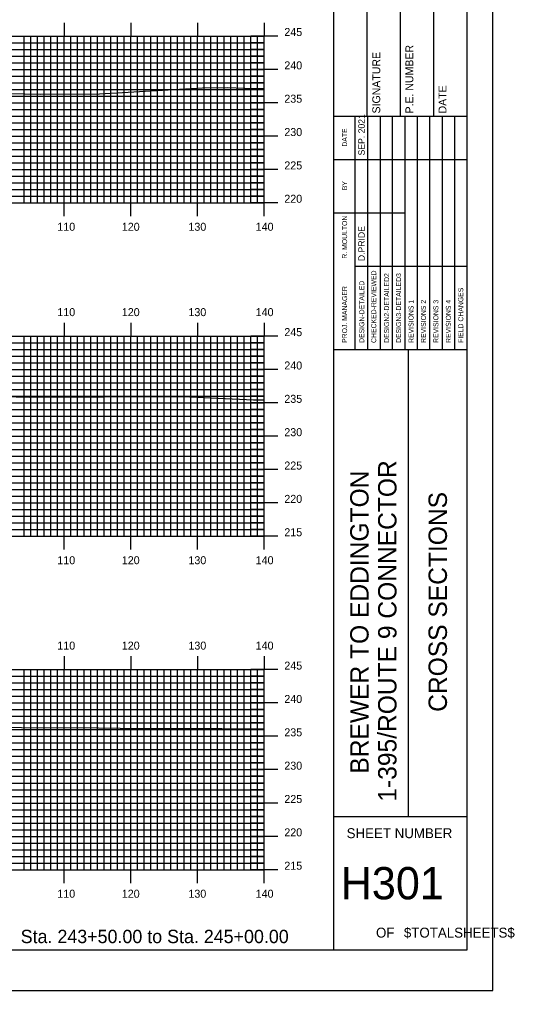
# Model space of a CAD drawing. Extents: x 1802716 to 1803060, y 442591 to 442811.
# Drawn here: x 1802985.4 to 1803059.6, y 442590.5 to 442736.2 of the extents above; entities that cross this region are included whole.
import ezdxf

# ---------------------------------------------------------------- set-up
doc = ezdxf.new("R2010")
doc.units = 0
for name, color, linetype in [('BORDER', 7, 'Continuous'), ('H_V ANNOTATION', 7, 'Continuous'), ('MAJOR', 7, 'Continuous'), ('MINOR', 7, 'Continuous'), ('PLOT BOUNDARY', 7, 'Continuous'), ('S_Roadway_Centerline', 7, 'Continuous')]:
    doc.layers.add(name, color=color, linetype=linetype)

msp = doc.modelspace()

# ---------------------------------------------------------------- linework, layer by layer
at = {"layer": 'BORDER'}
for p, q in [((1803032.51, 442596.67), (1803032.51, 442806.67)), ((1803037.51, 442721.67), (1803037.51, 442738.97)), ((1803042.51, 442721.67), (1803042.51, 442738.97)), ((1803047.51, 442721.67), (1803047.51, 442738.97)), ((1803032.51, 442721.67), (1803052.51, 442721.67)), ((1803032.51, 442686.67), (1803052.51, 442686.67)), ((1803043.7, 442616.67), (1803043.7, 442686.67)), ((1803032.51, 442616.67), (1803052.51, 442616.67))]:
    msp.add_line(p, q, dxfattribs=at)
msp.add_lwpolyline([(1802732.51, 442596.67), (1803052.51, 442596.67), (1803052.51, 442806.67), (1802732.51, 442806.67)], close=True, dxfattribs=at)
for points in [[(1803035.74, 442715.17), (1803035.74, 442721.67)], [(1803037.61, 442686.68), (1803037.61, 442721.67)], [(1803039.47, 442721.67), (1803039.47, 442686.68)], [(1803041.34, 442686.68), (1803041.34, 442721.67)], [(1803043.2, 442686.68), (1803043.2, 442721.67)], [(1803045.06, 442686.68), (1803045.06, 442721.67)], [(1803046.93, 442686.68), (1803046.93, 442721.67)], [(1803048.79, 442686.68), (1803048.79, 442721.67)], [(1803050.65, 442686.68), (1803050.65, 442721.67)], [(1803035.75, 442686.68), (1803035.75, 442720.26)], [(1803032.51, 442715.17), (1803052.51, 442715.17)], [(1803032.51, 442707.17), (1803035.75, 442707.17)], [(1803035.74, 442707.17), (1803043.2, 442707.17)], [(1803035.74, 442699.17), (1803052.51, 442699.17)]]:
    msp.add_lwpolyline(points, dxfattribs=at)
at = {"layer": 'MAJOR'}
for p, q in [((1802992.11, 442735.67), (1802992.11, 442733.67)), ((1803002.11, 442735.67), (1803002.11, 442733.67)), ((1803012.11, 442735.67), (1803012.11, 442733.67)), ((1803022.11, 442735.67), (1803022.11, 442733.67)), ((1802742.11, 442733.67), (1803022.11, 442733.67)), ((1802742.11, 442733.67), (1803022.11, 442733.67)), ((1802992.11, 442708.67), (1802992.11, 442733.67)), ((1803002.11, 442708.67), (1803002.11, 442733.67)), ((1803012.11, 442708.67), (1803012.11, 442733.67)), ((1803024.12, 442733.67), (1803020.11, 442733.67)), ((1803022.11, 442708.67), (1803022.11, 442733.67)), ((1803022.11, 442708.67), (1803022.11, 442733.67)), ((1802742.11, 442728.67), (1803022.11, 442728.67)), ((1803024.12, 442728.67), (1803020.11, 442728.67)), ((1802742.11, 442723.67), (1803022.11, 442723.67)), ((1803024.12, 442723.67), (1803020.11, 442723.67)), ((1802742.11, 442718.67), (1803022.11, 442718.67)), ((1803024.12, 442718.67), (1803020.11, 442718.67)), ((1802742.11, 442713.67), (1803022.11, 442713.67)), ((1803024.12, 442713.67), (1803020.11, 442713.67)), ((1802742.11, 442708.67), (1803022.11, 442708.67)), ((1802742.11, 442708.67), (1803022.11, 442708.67)), ((1802992.11, 442706.66), (1802992.11, 442708.67)), ((1803002.11, 442706.66), (1803002.11, 442708.67)), ((1803012.11, 442706.66), (1803012.11, 442708.67)), ((1803024.12, 442708.67), (1803020.11, 442708.67)), ((1803022.11, 442706.66), (1803022.11, 442708.67)), ((1802992.11, 442690.67), (1802992.11, 442688.67)), ((1803002.11, 442690.67), (1803002.11, 442688.67)), ((1803012.11, 442690.67), (1803012.11, 442688.67)), ((1803022.11, 442690.67), (1803022.11, 442688.67)), ((1802742.11, 442688.67), (1803022.11, 442688.67)), ((1802742.11, 442688.67), (1803022.11, 442688.67)), ((1802992.11, 442658.67), (1802992.11, 442688.67)), ((1803002.11, 442658.67), (1803002.11, 442688.67)), ((1803012.11, 442658.67), (1803012.11, 442688.67)), ((1803024.12, 442688.67), (1803020.11, 442688.67)), ((1803022.11, 442658.67), (1803022.11, 442688.67)), ((1803022.11, 442658.67), (1803022.11, 442688.67)), ((1802742.11, 442683.67), (1803022.11, 442683.67)), ((1803024.12, 442683.67), (1803020.11, 442683.67)), ((1802742.11, 442678.67), (1803022.11, 442678.67)), ((1803024.12, 442678.67), (1803020.11, 442678.67)), ((1802742.11, 442673.67), (1803022.11, 442673.67)), ((1803024.12, 442673.67), (1803020.11, 442673.67)), ((1802742.11, 442668.67), (1803022.11, 442668.67)), ((1803024.12, 442668.67), (1803020.11, 442668.67)), ((1802742.11, 442663.67), (1803022.11, 442663.67)), ((1803024.12, 442663.67), (1803020.11, 442663.67)), ((1802742.11, 442658.67), (1803022.11, 442658.67)), ((1802742.11, 442658.67), (1803022.11, 442658.67)), ((1802992.11, 442656.66), (1802992.11, 442658.67)), ((1803002.11, 442656.66), (1803002.11, 442658.67)), ((1803012.11, 442656.66), (1803012.11, 442658.67)), ((1803024.12, 442658.67), (1803020.11, 442658.67)), ((1803022.11, 442656.66), (1803022.11, 442658.67)), ((1802992.11, 442640.67), (1802992.11, 442638.67)), ((1803002.11, 442640.67), (1803002.11, 442638.67)), ((1803012.11, 442640.67), (1803012.11, 442638.67)), ((1803022.11, 442640.67), (1803022.11, 442638.67)), ((1802742.11, 442638.67), (1803022.11, 442638.67)), ((1802742.11, 442638.67), (1803022.11, 442638.67)), ((1802992.11, 442608.67), (1802992.11, 442638.67)), ((1803002.11, 442608.67), (1803002.11, 442638.67)), ((1803012.11, 442608.67), (1803012.11, 442638.67)), ((1803024.12, 442638.67), (1803020.11, 442638.67)), ((1803022.11, 442608.67), (1803022.11, 442638.67)), ((1803022.11, 442608.67), (1803022.11, 442638.67)), ((1802742.11, 442633.67), (1803022.11, 442633.67)), ((1803024.12, 442633.67), (1803020.11, 442633.67)), ((1802742.11, 442628.67), (1803022.11, 442628.67)), ((1803024.12, 442628.67), (1803020.11, 442628.67)), ((1802742.11, 442623.67), (1803022.11, 442623.67)), ((1803024.12, 442623.67), (1803020.11, 442623.67)), ((1802742.11, 442618.67), (1803022.11, 442618.67)), ((1803024.12, 442618.67), (1803020.11, 442618.67)), ((1802742.11, 442613.67), (1803022.11, 442613.67)), ((1803024.12, 442613.67), (1803020.11, 442613.67)), ((1802742.11, 442608.67), (1803022.11, 442608.67)), ((1802742.11, 442608.67), (1803022.11, 442608.67)), ((1802992.11, 442606.66), (1802992.11, 442608.67)), ((1803002.11, 442606.66), (1803002.11, 442608.67)), ((1803012.11, 442606.66), (1803012.11, 442608.67)), ((1803024.12, 442608.67), (1803020.11, 442608.67)), ((1803022.11, 442606.66), (1803022.11, 442608.67))]:
    msp.add_line(p, q, dxfattribs=at)
at = {"layer": 'MINOR'}
for p, q in [((1802742.11, 442732.67), (1803022.11, 442732.67)), ((1802986.11, 442708.67), (1802986.11, 442733.67)), ((1802987.11, 442708.67), (1802987.11, 442733.67)), ((1802988.11, 442708.67), (1802988.11, 442733.67)), ((1802989.11, 442708.67), (1802989.11, 442733.67)), ((1802990.11, 442708.67), (1802990.11, 442733.67)), ((1802991.11, 442708.67), (1802991.11, 442733.67)), ((1802993.11, 442708.67), (1802993.11, 442733.67)), ((1802994.11, 442708.67), (1802994.11, 442733.67)), ((1802995.11, 442708.67), (1802995.11, 442733.67)), ((1802996.11, 442708.67), (1802996.11, 442733.67)), ((1802997.11, 442708.67), (1802997.11, 442733.67)), ((1802998.11, 442708.67), (1802998.11, 442733.67)), ((1802999.11, 442708.67), (1802999.11, 442733.67)), ((1803000.11, 442708.67), (1803000.11, 442733.67)), ((1803001.11, 442708.67), (1803001.11, 442733.67)), ((1803003.11, 442708.67), (1803003.11, 442733.67)), ((1803004.11, 442708.67), (1803004.11, 442733.67)), ((1803005.11, 442708.67), (1803005.11, 442733.67)), ((1803006.11, 442708.67), (1803006.11, 442733.67)), ((1803007.11, 442708.67), (1803007.11, 442733.67)), ((1803008.11, 442708.67), (1803008.11, 442733.67)), ((1803009.11, 442708.67), (1803009.11, 442733.67)), ((1803010.11, 442708.67), (1803010.11, 442733.67)), ((1803011.11, 442708.67), (1803011.11, 442733.67)), ((1803013.11, 442708.67), (1803013.11, 442733.67)), ((1803014.11, 442708.67), (1803014.11, 442733.67)), ((1803015.11, 442708.67), (1803015.11, 442733.67)), ((1803016.11, 442708.67), (1803016.11, 442733.67)), ((1803017.11, 442708.67), (1803017.11, 442733.67)), ((1803018.11, 442708.67), (1803018.11, 442733.67)), ((1803019.11, 442708.67), (1803019.11, 442733.67)), ((1803020.11, 442708.67), (1803020.11, 442733.67)), ((1803022.11, 442732.67), (1803020.11, 442732.67)), ((1803021.11, 442708.67), (1803021.11, 442733.67)), ((1802742.11, 442731.67), (1803022.11, 442731.67)), ((1803022.11, 442731.67), (1803020.11, 442731.67)), ((1802742.11, 442730.67), (1803022.11, 442730.67)), ((1803022.11, 442730.67), (1803020.11, 442730.67)), ((1802742.11, 442729.67), (1803022.11, 442729.67)), ((1803022.11, 442729.67), (1803020.11, 442729.67)), ((1802742.11, 442727.67), (1803022.11, 442727.67)), ((1803022.11, 442727.67), (1803020.11, 442727.67)), ((1802742.11, 442726.67), (1803022.11, 442726.67)), ((1802742.11, 442725.67), (1803022.11, 442725.67)), ((1803022.11, 442726.67), (1803020.11, 442726.67)), ((1803022.11, 442725.67), (1803020.11, 442725.67)), ((1802742.11, 442724.67), (1803022.11, 442724.67)), ((1803022.11, 442724.67), (1803020.11, 442724.67)), ((1802742.11, 442722.67), (1803022.11, 442722.67)), ((1803022.11, 442722.67), (1803020.11, 442722.67)), ((1802742.11, 442721.67), (1803022.11, 442721.67)), ((1803022.11, 442721.67), (1803020.11, 442721.67)), ((1802742.11, 442720.67), (1803022.11, 442720.67)), ((1802742.11, 442719.67), (1803022.11, 442719.67)), ((1803022.11, 442720.67), (1803020.11, 442720.67)), ((1803022.11, 442719.67), (1803020.11, 442719.67)), ((1802742.11, 442717.67), (1803022.11, 442717.67)), ((1802742.11, 442716.67), (1803022.11, 442716.67)), ((1803022.11, 442717.67), (1803020.11, 442717.67)), ((1803022.11, 442716.67), (1803020.11, 442716.67)), ((1802742.11, 442715.67), (1803022.11, 442715.67)), ((1803022.11, 442715.67), (1803020.11, 442715.67)), ((1802742.11, 442714.67), (1803022.11, 442714.67)), ((1803022.11, 442714.67), (1803020.11, 442714.67)), ((1802742.11, 442712.67), (1803022.11, 442712.67)), ((1803022.11, 442712.67), (1803020.11, 442712.67)), ((1802742.11, 442711.67), (1803022.11, 442711.67)), ((1803022.11, 442711.67), (1803020.11, 442711.67)), ((1802742.11, 442710.67), (1803022.11, 442710.67)), ((1802742.11, 442709.67), (1803022.11, 442709.67)), ((1803022.11, 442710.67), (1803020.11, 442710.67)), ((1803022.11, 442709.67), (1803020.11, 442709.67)), ((1802742.11, 442687.67), (1803022.11, 442687.67)), ((1802986.11, 442658.67), (1802986.11, 442688.67)), ((1802987.11, 442658.67), (1802987.11, 442688.67)), ((1802988.11, 442658.67), (1802988.11, 442688.67)), ((1802989.11, 442658.67), (1802989.11, 442688.67)), ((1802990.11, 442658.67), (1802990.11, 442688.67)), ((1802991.11, 442658.67), (1802991.11, 442688.67)), ((1802993.11, 442658.67), (1802993.11, 442688.67)), ((1802994.11, 442658.67), (1802994.11, 442688.67)), ((1802995.11, 442658.67), (1802995.11, 442688.67)), ((1802996.11, 442658.67), (1802996.11, 442688.67)), ((1802997.11, 442658.67), (1802997.11, 442688.67)), ((1802998.11, 442658.67), (1802998.11, 442688.67)), ((1802999.11, 442658.67), (1802999.11, 442688.67)), ((1803000.11, 442658.67), (1803000.11, 442688.67)), ((1803001.11, 442658.67), (1803001.11, 442688.67)), ((1803003.11, 442658.67), (1803003.11, 442688.67)), ((1803004.11, 442658.67), (1803004.11, 442688.67)), ((1803005.11, 442658.67), (1803005.11, 442688.67)), ((1803006.11, 442658.67), (1803006.11, 442688.67)), ((1803007.11, 442658.67), (1803007.11, 442688.67)), ((1803008.11, 442658.67), (1803008.11, 442688.67)), ((1803009.11, 442658.67), (1803009.11, 442688.67)), ((1803010.11, 442658.67), (1803010.11, 442688.67)), ((1803011.11, 442658.67), (1803011.11, 442688.67)), ((1803013.11, 442658.67), (1803013.11, 442688.67)), ((1803014.11, 442658.67), (1803014.11, 442688.67)), ((1803015.11, 442658.67), (1803015.11, 442688.67)), ((1803016.11, 442658.67), (1803016.11, 442688.67)), ((1803017.11, 442658.67), (1803017.11, 442688.67)), ((1803018.11, 442658.67), (1803018.11, 442688.67)), ((1803019.11, 442658.67), (1803019.11, 442688.67)), ((1803020.11, 442658.67), (1803020.11, 442688.67)), ((1803022.11, 442687.67), (1803020.11, 442687.67)), ((1803021.11, 442658.67), (1803021.11, 442688.67)), ((1802742.11, 442686.67), (1803022.11, 442686.67)), ((1803022.11, 442686.67), (1803020.11, 442686.67)), ((1802742.11, 442685.67), (1803022.11, 442685.67)), ((1802742.11, 442684.67), (1803022.11, 442684.67)), ((1803022.11, 442685.67), (1803020.11, 442685.67)), ((1803022.11, 442684.67), (1803020.11, 442684.67)), ((1802742.11, 442682.67), (1803022.11, 442682.67)), ((1802742.11, 442681.67), (1803022.11, 442681.67)), ((1803022.11, 442682.67), (1803020.11, 442682.67)), ((1803022.11, 442681.67), (1803020.11, 442681.67)), ((1802742.11, 442680.67), (1803022.11, 442680.67)), ((1803022.11, 442680.67), (1803020.11, 442680.67)), ((1802742.11, 442679.67), (1803022.11, 442679.67)), ((1803022.11, 442679.67), (1803020.11, 442679.67)), ((1802742.11, 442677.67), (1803022.11, 442677.67)), ((1803022.11, 442677.67), (1803020.11, 442677.67)), ((1802742.11, 442676.67), (1803022.11, 442676.67)), ((1803022.11, 442676.67), (1803020.11, 442676.67)), ((1802742.11, 442675.67), (1803022.11, 442675.67)), ((1802742.11, 442674.67), (1803022.11, 442674.67)), ((1803022.11, 442675.67), (1803020.11, 442675.67)), ((1803022.11, 442674.67), (1803020.11, 442674.67)), ((1802742.11, 442672.67), (1803022.11, 442672.67)), ((1802742.11, 442671.67), (1803022.11, 442671.67)), ((1803022.11, 442672.67), (1803020.11, 442672.67)), ((1803022.11, 442671.67), (1803020.11, 442671.67)), ((1802742.11, 442670.67), (1803022.11, 442670.67)), ((1803022.11, 442670.67), (1803020.11, 442670.67)), ((1802742.11, 442669.67), (1803022.11, 442669.67)), ((1803022.11, 442669.67), (1803020.11, 442669.67)), ((1802742.11, 442667.67), (1803022.11, 442667.67)), ((1803022.11, 442667.67), (1803020.11, 442667.67)), ((1802742.11, 442666.67), (1803022.11, 442666.67)), ((1802742.11, 442665.67), (1803022.11, 442665.67)), ((1803022.11, 442666.67), (1803020.11, 442666.67)), ((1803022.11, 442665.67), (1803020.11, 442665.67)), ((1802742.11, 442664.67), (1803022.11, 442664.67)), ((1803022.11, 442664.67), (1803020.11, 442664.67)), ((1802742.11, 442662.67), (1803022.11, 442662.67)), ((1802742.11, 442661.67), (1803022.11, 442661.67)), ((1803022.11, 442662.67), (1803020.11, 442662.67)), ((1803022.11, 442661.67), (1803020.11, 442661.67)), ((1802742.11, 442660.67), (1803022.11, 442660.67)), ((1803022.11, 442660.67), (1803020.11, 442660.67)), ((1802742.11, 442659.67), (1803022.11, 442659.67)), ((1803022.11, 442659.67), (1803020.11, 442659.67)), ((1802986.11, 442608.67), (1802986.11, 442638.67)), ((1802987.11, 442608.67), (1802987.11, 442638.67)), ((1802988.11, 442608.67), (1802988.11, 442638.67)), ((1802989.11, 442608.67), (1802989.11, 442638.67)), ((1802990.11, 442608.67), (1802990.11, 442638.67)), ((1802991.11, 442608.67), (1802991.11, 442638.67)), ((1802993.11, 442608.67), (1802993.11, 442638.67)), ((1802994.11, 442608.67), (1802994.11, 442638.67)), ((1802995.11, 442608.67), (1802995.11, 442638.67)), ((1802996.11, 442608.67), (1802996.11, 442638.67)), ((1802997.11, 442608.67), (1802997.11, 442638.67)), ((1802998.11, 442608.67), (1802998.11, 442638.67)), ((1802999.11, 442608.67), (1802999.11, 442638.67)), ((1803000.11, 442608.67), (1803000.11, 442638.67)), ((1803001.11, 442608.67), (1803001.11, 442638.67)), ((1803003.11, 442608.67), (1803003.11, 442638.67)), ((1803004.11, 442608.67), (1803004.11, 442638.67)), ((1803005.11, 442608.67), (1803005.11, 442638.67)), ((1803006.11, 442608.67), (1803006.11, 442638.67)), ((1803007.11, 442608.67), (1803007.11, 442638.67)), ((1803008.11, 442608.67), (1803008.11, 442638.67)), ((1803009.11, 442608.67), (1803009.11, 442638.67)), ((1803010.11, 442608.67), (1803010.11, 442638.67)), ((1803011.11, 442608.67), (1803011.11, 442638.67)), ((1803013.11, 442608.67), (1803013.11, 442638.67)), ((1803014.11, 442608.67), (1803014.11, 442638.67)), ((1803015.11, 442608.67), (1803015.11, 442638.67)), ((1803016.11, 442608.67), (1803016.11, 442638.67)), ((1803017.11, 442608.67), (1803017.11, 442638.67)), ((1803018.11, 442608.67), (1803018.11, 442638.67)), ((1803019.11, 442608.67), (1803019.11, 442638.67)), ((1803020.11, 442608.67), (1803020.11, 442638.67)), ((1803021.11, 442608.67), (1803021.11, 442638.67)), ((1802742.11, 442637.67), (1803022.11, 442637.67)), ((1802742.11, 442636.67), (1803022.11, 442636.67)), ((1803022.11, 442637.67), (1803020.11, 442637.67)), ((1803022.11, 442636.67), (1803020.11, 442636.67)), ((1802742.11, 442635.67), (1803022.11, 442635.67)), ((1803022.11, 442635.67), (1803020.11, 442635.67)), ((1802742.11, 442634.67), (1803022.11, 442634.67)), ((1803022.11, 442634.67), (1803020.11, 442634.67)), ((1802742.11, 442632.67), (1803022.11, 442632.67)), ((1803022.11, 442632.67), (1803020.11, 442632.67)), ((1802742.11, 442631.67), (1803022.11, 442631.67)), ((1802742.11, 442630.67), (1803022.11, 442630.67)), ((1803022.11, 442631.67), (1803020.11, 442631.67)), ((1803022.11, 442630.67), (1803020.11, 442630.67)), ((1802742.11, 442629.67), (1803022.11, 442629.67)), ((1803022.11, 442629.67), (1803020.11, 442629.67)), ((1802742.11, 442627.67), (1803022.11, 442627.67)), ((1802742.11, 442626.67), (1803022.11, 442626.67)), ((1803022.11, 442627.67), (1803020.11, 442627.67)), ((1803022.11, 442626.67), (1803020.11, 442626.67)), ((1802742.11, 442625.67), (1803022.11, 442625.67)), ((1803022.11, 442625.67), (1803020.11, 442625.67)), ((1802742.11, 442624.67), (1803022.11, 442624.67)), ((1803022.11, 442624.67), (1803020.11, 442624.67)), ((1802742.11, 442622.67), (1803022.11, 442622.67)), ((1803022.11, 442622.67), (1803020.11, 442622.67)), ((1802742.11, 442621.67), (1803022.11, 442621.67)), ((1802742.11, 442620.67), (1803022.11, 442620.67)), ((1803022.11, 442621.67), (1803020.11, 442621.67)), ((1803022.11, 442620.67), (1803020.11, 442620.67)), ((1802742.11, 442619.67), (1803022.11, 442619.67)), ((1803022.11, 442619.67), (1803020.11, 442619.67)), ((1802742.11, 442617.67), (1803022.11, 442617.67)), ((1803022.11, 442617.67), (1803020.11, 442617.67)), ((1802742.11, 442616.67), (1803022.11, 442616.67)), ((1803022.11, 442616.67), (1803020.11, 442616.67)), ((1802742.11, 442615.67), (1803022.11, 442615.67)), ((1802742.11, 442614.67), (1803022.11, 442614.67)), ((1803022.11, 442615.67), (1803020.11, 442615.67)), ((1803022.11, 442614.67), (1803020.11, 442614.67)), ((1802742.11, 442612.67), (1803022.11, 442612.67)), ((1803022.11, 442612.67), (1803020.11, 442612.67)), ((1802742.11, 442611.67), (1803022.11, 442611.67)), ((1802742.11, 442610.67), (1803022.11, 442610.67)), ((1803022.11, 442611.67), (1803020.11, 442611.67)), ((1803022.11, 442610.67), (1803020.11, 442610.67)), ((1802742.11, 442609.67), (1803022.11, 442609.67)), ((1803022.11, 442609.67), (1803020.11, 442609.67))]:
    msp.add_line(p, q, dxfattribs=at)
at = {"layer": 'PLOT BOUNDARY'}
msp.add_lwpolyline([(1802716.33, 442590.55), (1803056.33, 442590.55), (1803056.33, 442810.55), (1802716.33, 442810.55)], close=True, dxfattribs=at)
at = {"layer": 'S_Roadway_Centerline'}
for points in [[(1802912.77, 442724.61), (1802916.02, 442724.62), (1802924.01, 442725.01), (1802933.66, 442724.89), (1802935.41, 442724.92), (1802937.02, 442724.93), (1802949.42, 442725.08), (1802955.6, 442725), (1802958.79, 442724.98), (1802962.12, 442725.03), (1802977.09, 442725.21), (1802988.55, 442724.96), (1802997.4, 442725.02), (1803012.84, 442725.92), (1803016.56, 442725.93), (1803019.18, 442725.87), (1803022.11, 442725.79)], [(1802911.28, 442679.52), (1802917.62, 442679.58), (1802925.71, 442679.57), (1802929.64, 442679.54), (1802932.71, 442679.52), (1802951.63, 442679.6), (1802952.9, 442679.63), (1802953.84, 442679.63), (1802964.67, 442679.72), (1802974.72, 442679.8), (1802976.64, 442679.76), (1802986.96, 442679.51), (1802997.7, 442679.57), (1802997.9, 442679.57), (1802998.07, 442679.57), (1803009.89, 442679.63), (1803020.47, 442679.14), (1803022.11, 442679.13)], [(1802912.36, 442629.71), (1802922.39, 442629.64), (1802933.82, 442629.87), (1802933.98, 442629.88), (1802934.17, 442629.87), (1802955.33, 442629.75), (1802959.01, 442629.86), (1802969.01, 442630.16), (1802976.45, 442630.07), (1802985.74, 442629.98), (1802997.29, 442629.92), (1803003.78, 442629.83), (1803011.94, 442629.84), (1803015.73, 442629.82), (1803018.95, 442629.8), (1803022.11, 442629.8)]]:
    msp.add_lwpolyline(points, dxfattribs=at)

# ---------------------------------------------------------------- texts
at = {"layer": 'BORDER'}
for s, height, p in [('SIGNATURE', 1.181, (1803039.48, 442722.06)), ('P.E. NUMBER', 1.1811, (1803044.44, 442722.06)), ('DATE', 1.181, (1803049.4, 442722.06)), ('SEP. 2021', 0.969, (1803037.16, 442715.76)), ('DATE', 0.743, (1803034.52, 442717.08)), ('BY', 0.743, (1803034.52, 442710.54)), ('R. MOULTON', 0.745, (1803034.52, 442700.28)), ('D.PRIDE', 0.969, (1803037.16, 442699.92)), ('CHECKED-REVIEWED', 0.7455, (1803038.88, 442687.65)), ('DESIGN2-DETAILED2', 0.7455, (1803040.81, 442687.65)), ('DESIGN3-DETAILED3', 0.7455, (1803042.6, 442687.65)), ('DESIGN-DETAILED', 0.7455, (1803037.09, 442687.65)), ('PROJ. MANAGER', 0.7455, (1803034.52, 442687.65)), ('FIELD CHANGES', 0.7455, (1803051.92, 442687.65)), ('REVISIONS 1', 0.7455, (1803044.47, 442687.65)), ('REVISIONS 2', 0.7455, (1803046.33, 442687.65)), ('REVISIONS 3', 0.7455, (1803048.19, 442687.65)), ('REVISIONS 4', 0.7455, (1803050.06, 442687.65)), ('1-395/ROUTE 9 CONNECTOR', 2.7557, (1803041.92, 442618.87)), ('BREWER TO EDDINGTON', 2.7557, (1803037.74, 442623.07)), ('CROSS SECTIONS', 2.7557, (1803049.48, 442632.34))]:
    msp.add_text(s, height=height, rotation=90, dxfattribs=at).set_placement(p)
for s, height, p in [('SHEET NUMBER', 1.4905, (1803034.45, 442613.4)), ('H301', 4.839, (1803033.55, 442604.23)), ('$TOTALSHEETS$', 1.4905, (1803043.03, 442598.49)), ('OF', 1.491, (1803038.85, 442598.49))]:
    msp.add_text(s, height=height, dxfattribs=at).set_placement(p)
at = {"layer": 'H_V ANNOTATION'}
for s, height, p in [('245', 1.2, (1803025.11, 442733.67)), ('240', 1.2, (1803025.11, 442728.67)), ('235', 1.2, (1803025.11, 442723.67)), ('230', 1.2, (1803025.11, 442718.67)), ('225', 1.2, (1803025.11, 442713.67)), ('220', 1.2, (1803025.11, 442708.67)), ('110', 1.2, (1802991.1, 442704.47)), ('120', 1.2, (1803000.76, 442704.47)), ('130', 1.2, (1803010.74, 442704.47)), ('140', 1.2, (1803020.82, 442704.47)), ('110', 1.2, (1802991.1, 442691.67)), ('120', 1.2, (1803000.76, 442691.67)), ('130', 1.2, (1803010.74, 442691.67)), ('140', 1.2, (1803020.82, 442691.67)), ('245', 1.2, (1803025.11, 442688.67)), ('240', 1.2, (1803025.11, 442683.67)), ('235', 1.2, (1803025.11, 442678.67)), ('230', 1.2, (1803025.11, 442673.67)), ('225', 1.2, (1803025.11, 442668.67)), ('220', 1.2, (1803025.11, 442663.67)), ('215', 1.2, (1803025.11, 442658.67)), ('110', 1.2, (1802991.1, 442654.47)), ('120', 1.2, (1803000.76, 442654.47)), ('130', 1.2, (1803010.74, 442654.47)), ('140', 1.2, (1803020.82, 442654.47)), ('110', 1.2, (1802991.1, 442641.67)), ('120', 1.2, (1803000.76, 442641.67)), ('130', 1.2, (1803010.74, 442641.67)), ('140', 1.2, (1803020.82, 442641.67)), ('245', 1.2, (1803025.11, 442638.67)), ('240', 1.2, (1803025.11, 442633.67)), ('235', 1.2, (1803025.11, 442628.67)), ('230', 1.2, (1803025.11, 442623.67)), ('225', 1.2, (1803025.11, 442618.67)), ('220', 1.2, (1803025.11, 442613.67)), ('215', 1.2, (1803025.11, 442608.67)), ('110', 1.2, (1802991.1, 442604.47)), ('120', 1.2, (1803000.76, 442604.47)), ('130', 1.2, (1803010.74, 442604.47)), ('140', 1.2, (1803020.82, 442604.47)), ('Sta. 243+50.00 to Sta. 245+00.00', 2.0004, (1802985.61, 442597.66))]:
    msp.add_text(s, height=height, dxfattribs=at).set_placement(p)

doc.saveas('drawing.dxf')
